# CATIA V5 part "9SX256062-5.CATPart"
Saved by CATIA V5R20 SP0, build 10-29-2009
Part number: 9SX256062-5
Revision: ANY
Definition: UNKNOWN
Nomenclature: 9SX256062-5
Source: Unknown
Bounding box of the stored display mesh (mm): x -30 to 30, y -30 to 30, z -8 to 54
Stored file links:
  C:\Users\Utente\Desktop\IO LAVORO\3D X SITO CF\CUMSA\3D files SX.256062\SX 256062\9SX256062-5.CATPart
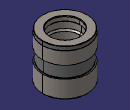
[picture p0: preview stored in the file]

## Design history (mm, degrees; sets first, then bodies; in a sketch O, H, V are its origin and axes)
Body1 "Redondeo4" (main body)
  Solid1: solid without history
